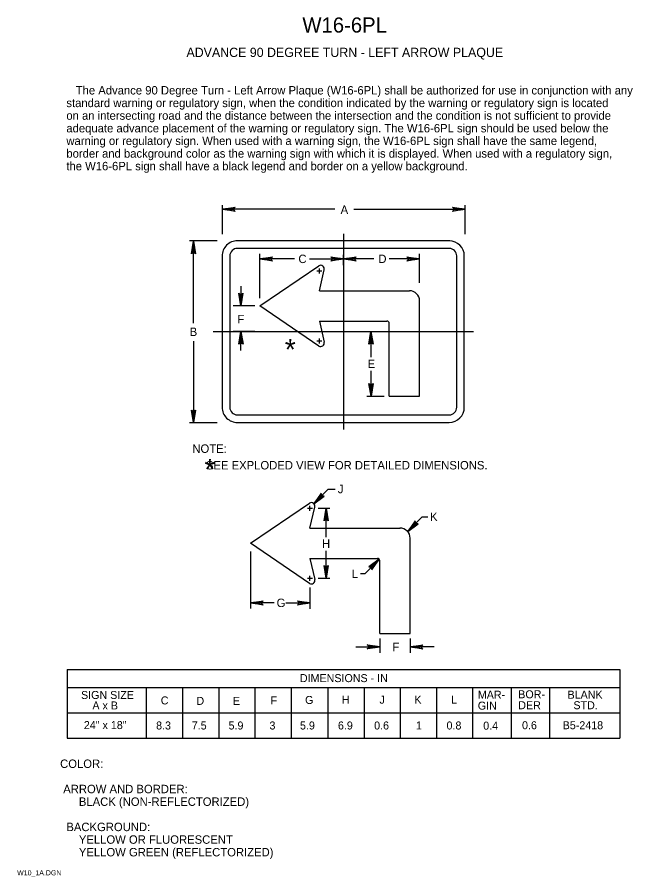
# Model space of a CAD drawing. Extents: x 0.013 to 0.195, y 0.004 to 0.259.
import ezdxf

# ---------------------------------------------------------------- set-up
doc = ezdxf.new("R2010")
doc.units = 0
for name, color, linetype in [('1', 7, 'Continuous'), ('2', 7, 'Continuous'), ('3', 7, 'Continuous')]:
    doc.layers.add(name, color=color, linetype=linetype)

# ---------------------------------------------------------------- blocks, each defined once
blk = doc.blocks.new('RARROW')
at = {"layer": '3'}
for p, q in [((-2.156, 0.28500000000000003), (-2.2665, 0.384625)), ((-2.2665, 0.384625), (0, 0)), ((0, 0), (-2.2665, -0.379125)), ((-2.156, 0.28500000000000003), (-2.075625, 0.12075)), ((0, 0), (-2.156, 0.28500000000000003)), ((-2.14975, -0.2705), (0, 0)), ((-2.075625, 0.12075), (0, 0)), ((0, 0), (-2.074, -0.108)), ((-2.2665, -0.379125), (-2.14975, -0.2705)), ((-2.074, -0.108), (-2.14975, -0.2705))]:
    blk.add_line(p, q, dxfattribs=at)

msp = doc.modelspace()

# ---------------------------------------------------------------- linework, layer by layer
at = {"layer": '1'}
for p, q in [((0.10950949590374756, 0.19475368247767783), (0.10950949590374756, 0.13669624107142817)), ((0.10234676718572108, 0.17787309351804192), (0.12908449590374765, 0.17787309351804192)), ((0.10234676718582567, 0.16887309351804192), (0.12233946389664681, 0.16887309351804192)), ((0.07079216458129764, 0.16574452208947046), (0.14811133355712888, 0.16574452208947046)), ((0.1230844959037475, 0.1466010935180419), (0.1320844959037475, 0.14660109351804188)), ((0.09955074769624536, 0.10743259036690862), (0.12628847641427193, 0.10743259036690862)), ((0.09955074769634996, 0.09843259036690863), (0.11954344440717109, 0.09843259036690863)), ((0.12028847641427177, 0.07616059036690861), (0.12928847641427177, 0.07616059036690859))]:
    msp.add_line(p, q, dxfattribs=at)
for centre, radius, start, end in [((0.12908449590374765, 0.1748730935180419), 0.0029999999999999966, 0, 90.49186611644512), ((0.1223344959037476, 0.16812309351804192), 0.0007499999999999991, 89.80726044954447, 89.80726044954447), ((0.1223344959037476, 0.16812309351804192), 0.0007499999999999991, 89.74434961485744, 89.74483937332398), ((0.1223344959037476, 0.16812309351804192), 0.0007499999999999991, 2.2168933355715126e-12, 89.6204705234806), ((0.12628847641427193, 0.1044325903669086), 0.0029999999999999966, 0, 90.49186611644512), ((0.11953847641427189, 0.09768259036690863), 0.0007499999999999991, 89.80726044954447, 89.80726044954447), ((0.11953847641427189, 0.09768259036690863), 0.0007499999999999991, 89.74434961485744, 89.74483937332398), ((0.11953847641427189, 0.09768259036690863), 0.0007499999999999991, 2.2168933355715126e-12, 89.6204705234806)]:
    msp.add_arc(centre, radius, start, end, dxfattribs=at)
at = {"layer": '3'}
for p, q in [((0.07359843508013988, 0.1946907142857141), (0.07359843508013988, 0.20331284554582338)), ((0.10689328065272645, 0.20206284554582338), (0.07363359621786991, 0.20206284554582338)), ((0.1125947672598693, 0.20206284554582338), (0.1455984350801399, 0.20206284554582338)), ((0.1455984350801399, 0.1946907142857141), (0.1455984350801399, 0.20331284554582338)), ((0.07196701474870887, 0.19268784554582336), (0.0637585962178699, 0.19268784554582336)), ((0.0650085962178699, 0.1682504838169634), (0.0650085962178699, 0.19268784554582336)), ((0.14105197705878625, 0.1926907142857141), (0.07796701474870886, 0.1926907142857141)), ((0.14099731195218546, 0.1904407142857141), (0.07796701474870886, 0.1904407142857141)), ((0.0846506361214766, 0.1756636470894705), (0.0846506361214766, 0.1888582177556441)), ((0.1320844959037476, 0.18023608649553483), (0.1320844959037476, 0.1888582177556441)), ((0.07346701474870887, 0.1881907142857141), (0.07346701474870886, 0.14329059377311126)), ((0.07571701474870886, 0.1881907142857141), (0.07571701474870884, 0.14329059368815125)), ((0.09499236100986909, 0.18730692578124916), (0.0846506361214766, 0.18730692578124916)), ((0.09939918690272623, 0.18730692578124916), (0.10950949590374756, 0.18730692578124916)), ((0.10950749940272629, 0.1855104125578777), (0.10950749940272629, 0.18854687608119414)), ((0.11854522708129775, 0.18730692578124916), (0.10950949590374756, 0.18730692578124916)), ((0.1320844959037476, 0.18730692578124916), (0.1230516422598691, 0.18730692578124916)), ((0.14311543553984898, 0.14329446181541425), (0.14311543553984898, 0.18819458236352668)), ((0.14536543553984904, 0.14329446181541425), (0.145365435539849, 0.18819458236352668)), ((0.0846506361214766, 0.17337309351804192), (0.1021648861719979, 0.1852776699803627)), ((0.10161684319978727, 0.18376059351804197), (0.10233395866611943, 0.18376059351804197)), ((0.10233395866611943, 0.18376059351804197), (0.10233395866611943, 0.1844777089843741)), ((0.10233395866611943, 0.18304347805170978), (0.10233395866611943, 0.18376059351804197)), ((0.10233395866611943, 0.18376059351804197), (0.1030510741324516, 0.18376059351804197)), ((0.10234676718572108, 0.17787309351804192), (0.10377893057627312, 0.1840800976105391)), ((0.07902894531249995, 0.1792660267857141), (0.07902894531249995, 0.17337309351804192)), ((0.1320844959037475, 0.14660109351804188), (0.13208449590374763, 0.1748730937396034)), ((0.08316812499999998, 0.17337309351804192), (0.0767944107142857, 0.17337309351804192)), ((0.10216792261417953, 0.16145791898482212), (0.0846506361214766, 0.17337309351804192)), ((0.10234676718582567, 0.16887309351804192), (0.103778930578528, 0.16266608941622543)), ((0.1230844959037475, 0.1466010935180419), (0.12308449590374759, 0.16812309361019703)), ((0.08316812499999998, 0.16574678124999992), (0.0767944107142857, 0.16574678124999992)), ((0.07905234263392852, 0.1601288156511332), (0.07905234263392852, 0.16574452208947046)), ((0.10233395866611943, 0.16298559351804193), (0.10233395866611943, 0.1637027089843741)), ((0.116362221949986, 0.16574452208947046), (0.12151596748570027, 0.16574452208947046)), ((0.11765776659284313, 0.1657383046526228), (0.11765776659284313, 0.1581697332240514)), ((0.0650085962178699, 0.1629473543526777), (0.0650085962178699, 0.13885684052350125)), ((0.10161684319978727, 0.16298559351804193), (0.10233395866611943, 0.16298559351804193)), ((0.10233395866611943, 0.1622684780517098), (0.10233395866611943, 0.16298559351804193)), ((0.10233395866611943, 0.16298559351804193), (0.1030510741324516, 0.16298559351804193)), ((0.1176811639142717, 0.1466010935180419), (0.1176811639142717, 0.15407830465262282)), ((0.11638561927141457, 0.1466010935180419), (0.12153936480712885, 0.1466010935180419)), ((0.07796701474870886, 0.1410405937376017), (0.14086543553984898, 0.1410405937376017)), ((0.07196701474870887, 0.13868784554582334), (0.0637585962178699, 0.13868784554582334)), ((0.07796701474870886, 0.1387905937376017), (0.14086543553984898, 0.1387905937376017)), ((0.10065638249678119, 0.1146778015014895), (0.10491527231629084, 0.11901097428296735)), ((0.10491527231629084, 0.11901097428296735), (0.10697931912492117, 0.11901097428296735)), ((0.0818546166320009, 0.10293259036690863), (0.09936886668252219, 0.11483716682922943)), ((0.09882082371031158, 0.11332009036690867), (0.0995379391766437, 0.11332009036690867)), ((0.0995379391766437, 0.11332009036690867), (0.0995379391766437, 0.11403720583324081)), ((0.0995379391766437, 0.11332009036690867), (0.10025505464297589, 0.11332009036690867)), ((0.0995379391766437, 0.11260297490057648), (0.0995379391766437, 0.11332009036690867)), ((0.09955074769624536, 0.10743259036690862), (0.1009829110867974, 0.11363959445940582)), ((0.10201430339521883, 0.11332009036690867), (0.10545635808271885, 0.11332009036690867)), ((0.10433075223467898, 0.10473138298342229), (0.10433075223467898, 0.11251084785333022)), ((0.12855646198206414, 0.1064492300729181), (0.13281535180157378, 0.11078240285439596)), ((0.13281535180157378, 0.11078240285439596), (0.13448789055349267, 0.11078240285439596)), ((0.09937190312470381, 0.09101741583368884), (0.0818546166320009, 0.10293259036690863)), ((0.12928847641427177, 0.07616059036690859), (0.12928847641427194, 0.10443259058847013)), ((0.0818546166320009, 0.10050852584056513), (0.0818546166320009, 0.08358852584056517)), ((0.10433075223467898, 0.0925565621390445), (0.10433075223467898, 0.10068566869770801)), ((0.09955074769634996, 0.09843259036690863), (0.10098291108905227, 0.09222558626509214)), ((0.12007646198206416, 0.09819780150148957), (0.11581757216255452, 0.09386462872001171)), ((0.12028847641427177, 0.07616059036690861), (0.12028847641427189, 0.09768259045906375)), ((0.09882082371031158, 0.09254509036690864), (0.0995379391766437, 0.09254509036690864)), ((0.0995379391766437, 0.09254509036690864), (0.0995379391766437, 0.09326220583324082)), ((0.0995379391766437, 0.09182797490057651), (0.0995379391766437, 0.09254509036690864)), ((0.0995379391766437, 0.09254509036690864), (0.10025505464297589, 0.09254509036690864)), ((0.10201352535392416, 0.09254509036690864), (0.10545558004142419, 0.09254509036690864)), ((0.11581757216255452, 0.09386462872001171), (0.11457931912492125, 0.09386462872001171)), ((0.0995379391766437, 0.08985138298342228), (0.0995379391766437, 0.0834513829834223)), ((0.08887352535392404, 0.08521709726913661), (0.0818546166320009, 0.08521709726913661)), ((0.09242781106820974, 0.08521709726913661), (0.09956781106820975, 0.08521709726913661)), ((0.12028847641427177, 0.07465494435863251), (0.12028847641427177, 0.07041494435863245)), ((0.12928847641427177, 0.07465494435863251), (0.12928847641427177, 0.07041494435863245)), ((0.11316503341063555, 0.07218065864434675), (0.12030503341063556, 0.07218065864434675)), ((0.13642847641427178, 0.07218065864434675), (0.12928847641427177, 0.07218065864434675)), ((0.027461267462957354, 0.0654753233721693), (0.19155772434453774, 0.0654753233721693)), ((0.027461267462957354, 0.0654753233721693), (0.027461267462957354, 0.04510032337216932)), ((0.19155772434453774, 0.06547532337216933), (0.19155772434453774, 0.04510032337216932)), ((0.027461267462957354, 0.06010032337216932), (0.19155772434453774, 0.06010032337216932)), ((0.05096126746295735, 0.06010032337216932), (0.05096126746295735, 0.04510032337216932)), ((0.06171126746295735, 0.06010032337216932), (0.06171126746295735, 0.04510032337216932)), ((0.07246126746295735, 0.06010032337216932), (0.07246126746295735, 0.04510032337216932)), ((0.08321126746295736, 0.06010032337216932), (0.08321126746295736, 0.04510032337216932)), ((0.09396126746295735, 0.06010032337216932), (0.09396126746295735, 0.04510032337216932)), ((0.10483626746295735, 0.06010032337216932), (0.10483626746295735, 0.04510032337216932)), ((0.11558626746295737, 0.06010032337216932), (0.11558626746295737, 0.04510032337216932)), ((0.12633626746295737, 0.06010032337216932), (0.12633626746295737, 0.04510032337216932)), ((0.13708626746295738, 0.06010032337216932), (0.13708626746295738, 0.04510032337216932)), ((0.1478362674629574, 0.06010032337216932), (0.1478362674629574, 0.04510032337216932)), ((0.1592891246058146, 0.06010032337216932), (0.1592891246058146, 0.04510032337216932)), ((0.17062169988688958, 0.06010032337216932), (0.17062169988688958, 0.04510032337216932)), ((0.027461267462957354, 0.05260032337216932), (0.19155772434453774, 0.05260032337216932)), ((0.027461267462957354, 0.04510032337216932), (0.19155772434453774, 0.04510032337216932))]:
    msp.add_line(p, q, dxfattribs=at)
for centre, radius, start, end in [((0.07799927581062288, 0.1881623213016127), 0.004532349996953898, 89.64106666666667, 179.6410666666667), ((0.14086543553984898, 0.18819458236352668), 0.0045000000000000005, 0, 90), ((0.07799927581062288, 0.1881623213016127), 0.0022824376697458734, 89.28723611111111, 179.2872361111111), ((0.14086543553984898, 0.18819458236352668), 0.0022500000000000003, 0, 90), ((0.102718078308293, 0.18433678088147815), 0.0010914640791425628, 346.39815823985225, 120.45323601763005), ((0.102718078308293, 0.16240940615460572), 0.0010914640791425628, 239.54676398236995, 13.60184176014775), ((0.07799540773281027, 0.1433228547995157), 0.004528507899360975, 180.4081777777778, 270.40817777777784), ((0.07799540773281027, 0.1433228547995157), 0.002278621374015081, 180.81123055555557, 270.81123055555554), ((0.14086543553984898, 0.14329446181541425), 0.0045000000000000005, 270, 0), ((0.14086543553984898, 0.14329446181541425), 0.0022500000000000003, 270, 0), ((0.09992205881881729, 0.11389627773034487), 0.0010914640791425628, 346.39815823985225, 120.45323601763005), ((0.09992205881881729, 0.09196890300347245), 0.0010914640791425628, 239.54676398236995, 13.60184176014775)]:
    msp.add_arc(centre, radius, start, end, dxfattribs=at)

# ---------------------------------------------------------------- block references
for p, xscale, yscale, rotation in [((0.07359201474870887, 0.2020657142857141), 0.0016545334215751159, 0.0016366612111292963, 180), ((0.06496701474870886, 0.19256571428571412), 0.0016545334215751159, 0.0016366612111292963, 90), ((0.0846506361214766, 0.18730692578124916), 0.0016545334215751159, 0.0016366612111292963, 180), ((0.10950949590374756, 0.18730692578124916), 0.0016545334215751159, 0.0016366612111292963, 180), ((0.07902894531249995, 0.17337309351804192), 0.0016545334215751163, 0.0016366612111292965, -90.00000000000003), ((0.07905234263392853, 0.16574452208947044), 0.0016545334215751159, 0.0016366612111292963, 89.99999999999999), ((0.11765776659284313, 0.1657383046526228), 0.0016545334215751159, 0.0016366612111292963, 89.99999999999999), ((0.1176811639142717, 0.1466010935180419), 0.0016545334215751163, 0.0016366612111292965, -90.00000000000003), ((0.06496701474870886, 0.13873470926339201), 0.0016545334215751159, 0.0016366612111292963, -90), ((0.10065638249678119, 0.1146778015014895), 0.0016545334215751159, -0.0016366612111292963, -134.5046597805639), ((0.10434495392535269, 0.11334852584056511), 0.0016545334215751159, 0.0016366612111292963, 89.99999999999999), ((0.12855646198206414, 0.1064492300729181), 0.0016545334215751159, -0.0016366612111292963, -134.5046597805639), ((0.12007646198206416, 0.09819780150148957), 0.0016545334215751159, -0.0016366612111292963, 45.49534021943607), ((0.10433075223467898, 0.0925565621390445), 0.0016545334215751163, 0.0016366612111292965, -90.00000000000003), ((0.0818546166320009, 0.08521709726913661), 0.0016545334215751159, 0.0016366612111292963, 180), ((0.12928847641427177, 0.07218065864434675), 0.0016545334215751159, 0.0016366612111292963, 180)]:
    msp.add_blockref('RARROW', p, dxfattribs=dict(at, xscale=xscale, yscale=yscale, rotation=rotation))
at = {"layer": '3', "xscale": 0.0016545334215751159, "yscale": 0.0016366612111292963}
for p in [(0.1455984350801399, 0.20206284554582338), (0.10950949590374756, 0.18730692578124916), (0.1320844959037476, 0.18730692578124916), (0.09956781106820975, 0.08521709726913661), (0.12030503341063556, 0.07218065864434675)]:
    msp.add_blockref('RARROW', p, dxfattribs=at)

# ---------------------------------------------------------------- texts
at = {"layer": '1'}
for s, height, p in [('W16-6PL', 0.0045000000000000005, (0.0972959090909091, 0.2545)), ('ADVANCE 90 DEGREE TURN - LEFT ARROW PLAQUE', 0.00275025, (0.06288390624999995, 0.24725)), ('*', 0.006220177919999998, (0.09208226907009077, 0.15734780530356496)), ('*', 0.006220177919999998, (0.068223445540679, 0.12174596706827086)), ('COLOR:', 0.0024997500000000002, (0.025375, 0.036249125)), (' ARROW AND BORDER:', 0.0024997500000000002, (0.025375, 0.028749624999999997)), ('      BLACK (NON-REFLECTORIZED)', 0.0024997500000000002, (0.025375, 0.024999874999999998)), ('  BACKGROUND:', 0.0024997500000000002, (0.025375, 0.017500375)), ('      YELLOW OR FLUORESCENT ', 0.0024997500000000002, (0.025375, 0.013750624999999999)), ('      YELLOW GREEN (REFLECTORIZED)', 0.0024997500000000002, (0.025375, 0.010000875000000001)), ('W10_1A.DGN', 0.0015, (0.012625, 0.004375))]:
    msp.add_text(s, height=height, dxfattribs=at).set_placement(p)
at = {"layer": '2'}
for s, p in [('   The Advance 90 Degree Turn - Left Arrow Plaque (W16-6PL) shall be authorized for use in conjunction with any ', (0.027230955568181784, 0.23612525)), ('standard warning or regulatory sign, when the condition indicated by the warning or regulatory sign is located ', (0.027230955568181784, 0.23237549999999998)), ('on an intersecting road and the distance between the intersection and the condition is not sufficient to provide ', (0.027230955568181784, 0.22862575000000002)), ('adequate advance placement of the warning or regulatory sign. The W16-6PL sign should be used below the ', (0.027230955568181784, 0.22487600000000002)), ('warning or regulatory sign. When used with a warning sign, the W16-6PL sign shall have the same legend, ', (0.027230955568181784, 0.22112625)), ('border and background color as the warning sign with which it is displayed. When used with a regulatory sign, ', (0.027230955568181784, 0.2173765)), ('the W16-6PL sign shall have a black legend and border on a yellow background.', (0.027230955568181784, 0.21362675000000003))]:
    msp.add_text(s, height=0.0024997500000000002, dxfattribs=at).set_placement(p)
at = {"layer": '3'}
for s, height, p in [('A', 0.0024997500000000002, (0.10864247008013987, 0.2006907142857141)), ('C', 0.0024997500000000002, (0.09612310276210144, 0.18609318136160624)), ('D', 0.0024997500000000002, (0.11984103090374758, 0.18609318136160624)), ('F', 0.0024997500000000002, (0.0780333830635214, 0.16821161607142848)), ('B', 0.0024997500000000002, (0.06384201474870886, 0.16443797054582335)), ('E', 0.0024997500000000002, (0.1166622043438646, 0.15492293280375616)), ('NOTE:', 0.0024997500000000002, (0.06463573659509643, 0.1297688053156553)), ('   SEE EXPLODED VIEW FOR DETAILED DIMENSIONS.', 0.0024997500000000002, (0.06588351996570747, 0.12484576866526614)), ('H', 0.0024997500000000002, (0.10310530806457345, 0.10155780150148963)), ('L', 0.0024997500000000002, (0.11192605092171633, 0.09259780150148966)), ('G', 0.0024997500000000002, (0.08964708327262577, 0.08400335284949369)), ('F', 0.0024997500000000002, (0.12403929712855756, 0.07090281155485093)), ('DIMENSIONS - IN', 0.0023752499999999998, (0.09655178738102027, 0.06172532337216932)), ('SIGN SIZE', 0.0023752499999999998, (0.031586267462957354, 0.056725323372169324)), ('MAR-', 0.0023752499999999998, (0.14937191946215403, 0.05679995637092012)), ('BOR-', 0.0023752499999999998, (0.16137191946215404, 0.05692495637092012)), ('BLANK', 0.0023752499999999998, (0.1759969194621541, 0.05679995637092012)), ('C', 0.0023752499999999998, (0.05526438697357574, 0.05510032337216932)), ('D', 0.0023752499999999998, (0.06583626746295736, 0.05497532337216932)), ('E', 0.0023752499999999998, (0.07665626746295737, 0.05497532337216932)), ('F', 0.0023752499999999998, (0.08783626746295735, 0.05510032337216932)), ('G', 0.0023752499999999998, (0.09809912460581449, 0.05523883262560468)), ('H', 0.0023752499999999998, (0.10901438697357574, 0.055328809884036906)), ('J', 0.0023752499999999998, (0.12018977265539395, 0.055328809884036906)), ('K', 0.0023752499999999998, (0.1305323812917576, 0.055328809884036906)), ('L', 0.0023752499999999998, (0.14143713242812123, 0.055328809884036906)), ('A x B', 0.0023752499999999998, (0.03496126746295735, 0.05360032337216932)), ('GIN', 0.0023752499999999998, (0.14937191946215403, 0.053549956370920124)), ('DER', 0.0023752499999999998, (0.16137191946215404, 0.053674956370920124)), ('STD.', 0.0023752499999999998, (0.1777469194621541, 0.053674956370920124)), ('24" x 18"', 0.0023752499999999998, (0.03242261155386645, 0.04778769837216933)), ('8.3', 0.0023752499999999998, (0.05386432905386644, 0.047662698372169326)), ('7.5', 0.0023752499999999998, (0.06445765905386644, 0.047662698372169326)), ('5.9', 0.0023752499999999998, (0.07538052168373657, 0.047662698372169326)), ('3', 0.0023752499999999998, (0.08751788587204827, 0.047662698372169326)), ('5.9', 0.0023752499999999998, (0.09658337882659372, 0.047662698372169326)), ('6.9', 0.0023752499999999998, (0.10784695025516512, 0.047662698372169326)), ('0.6', 0.0023752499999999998, (0.1185933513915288, 0.047662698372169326)), ('1', 0.0023752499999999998, (0.13099379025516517, 0.047662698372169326)), ('0.8', 0.0023752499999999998, (0.1400803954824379, 0.047662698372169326)), ('0.4', 0.0023752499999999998, (0.1509789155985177, 0.04761233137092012)), ('0.6', 0.0023752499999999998, (0.16249043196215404, 0.04773733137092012)), ('B5-2418', 0.0023752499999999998, (0.17455728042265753, 0.04773733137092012))]:
    msp.add_text(s, height=height, dxfattribs=at).set_placement(p)
for s, p in [('J', (0.10781072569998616, 0.1177780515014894)), ('K', (0.1351850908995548, 0.10954948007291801))]:
    msp.add_text(s, height=0.0024997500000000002, rotation=360, dxfattribs=at).set_placement(p)

doc.saveas('drawing.dxf')
